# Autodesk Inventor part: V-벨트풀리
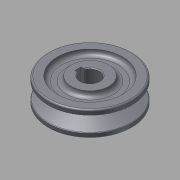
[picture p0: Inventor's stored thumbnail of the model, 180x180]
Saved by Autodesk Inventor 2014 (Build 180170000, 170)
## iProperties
Created: 2015-12
Part Number: V-벨트풀리
Material: 강철, 연강
Document SubType Name: Modeling
Designer: mdu
Density: 7.86 g/cm^3
Mass: 156.954 g
Surface Area: 99.5161 cm^2
Volume: 19.9687 cm^3
Appearance: Steel
CustomPartVersion: 1
Author: mdu
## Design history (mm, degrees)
sketch "주 스케치"
  geometry: L1 (0, 16)-(27, 16); L2 (27, 16)-(27, 12.861); L3 (27, 12.861)-(16, 9.498); L4 (16, 9.498)-(16, 6.502); L5 (16, 6.502)-(27, 3.139); L6 (27, 3.139)-(27, 0); L7 (27, 0)-(0, 0); L8 (25, 12.25)-(25, 3.75); L9 (16, 8)-(25, 8); L10 (27, 12.861)-(27, 3.139); L11 (0, -3)-(0, 18) reference; L12 (0, 0)-(0, 16)
  constraints: 22 end point, 5 perpendicular, 2 collinear, 2 midpoint, 2 point on line, 1 parallel
  dimensions: "d0" = 8.5 distance of L8.start L8.end (= da_Bw); "d1" = 34 deg angle of L3 L5 (= da_Alfa); "d2" = 2 distance between parallel lines of L2 L8 (= da_c); "d6" = 16 distance between parallel lines of L7 L1 (computed from d5, da_ng, da_Sg); "d21" = 50 diameter of L8 L11 (= da_Dw); "d25" = 11 distance between parallel lines of L4 L10 (= da_Hd); "d27" = 8 distance between parallel lines of L7 L9 (= da_Se)
node "벨트 평면"
revolve "본체" stored, may be unused: angle "d7" = 90 deg
revolve "그루브" stored, may be unused: angle "d15" = 90 deg
feature "허브 키홈"
fillet "모깎기3" dims "d28" = 0.5, "d29" = 1, "d30" = 1
sketch "스케치2"
  geometry: C1 r 12 at (0, 0); C2 r 21 at (0, 0); 1 further point
  constraints: 2 centre point, 2 coincident
  dimensions: "d31" = 24 diameter of C1; "d32" = 42 diameter of C2
extrude "돌출1" cut sketch "스케치2" distance "d33" = 3; taper "d34" = 0 deg
fillet "모깎기4" dims "d35" = 3
node "작업 평면2"
chamfer "모따기1" distance "d36" = 0.5; stored, may be unused: second distance "d37" = 2, angle "d38" = 45 deg
body "Solid1"
pattern_linear "그루브 패턴" dims "d18" = 12 (= da_Sg)
mirror "대칭1"
other parameters: "d5" = 8 (= da_Se), "da_Bw" = 8.5 [user parameter; used in 1 equation term], "da_Alfa" = 34 deg [user parameter; used in 1 equation term], "da_c" = 2 [user parameter; used in 1 equation term], "da_Dw" = 50 [user parameter; used in 1 equation term], "da_Hd" = 11 [user parameter; used in 1 equation term], "da_Se" = 8 [user parameter; used in 2 equation terms], "da_Sg" = 12 [user parameter; used in 2 equation terms], "da_r1" = 0 [user parameter], "da_r2" = 0 [user parameter], "d24" = 0, "d26" = 0
